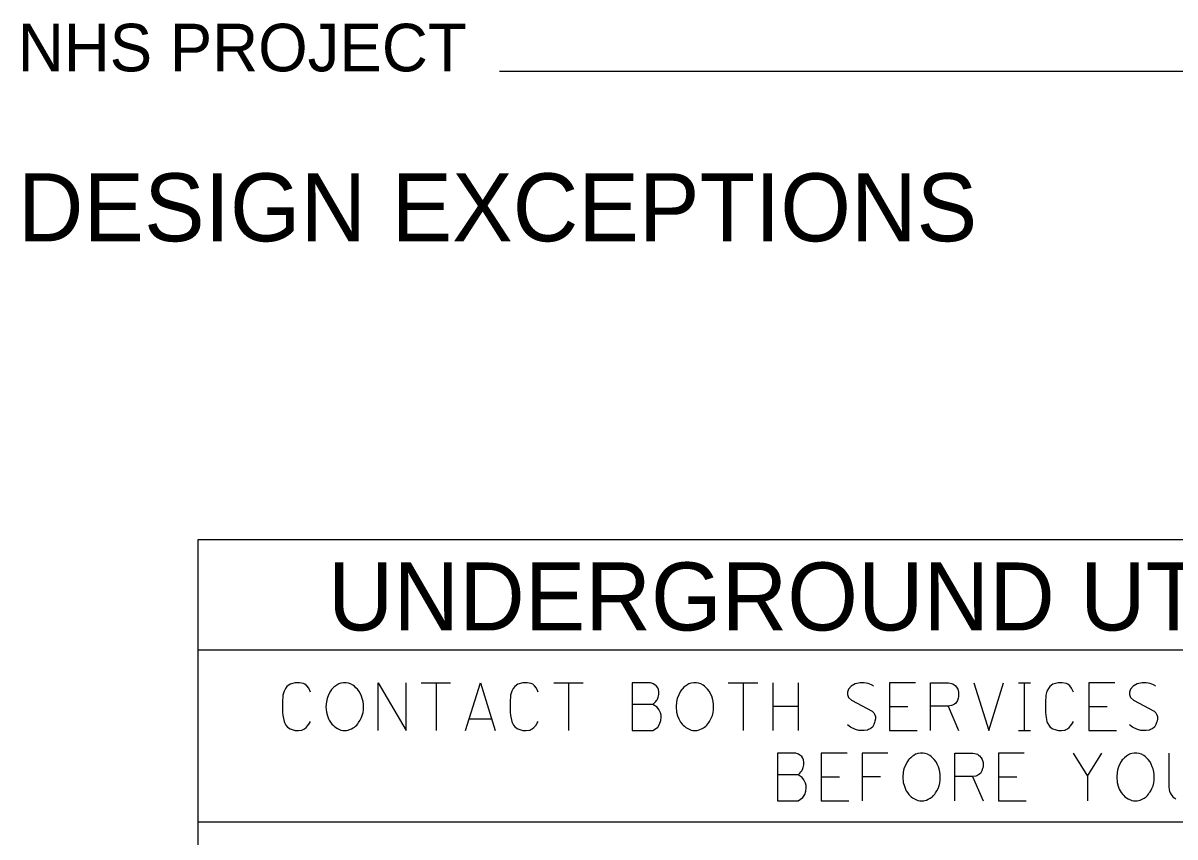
# Model space of a CAD drawing. Extents: x -97 to 34, y -21 to 22.
# Drawn here: x -97.447 to -94.056, y -17.539 to -15.144 of the extents above; entities that cross this region are included whole.
import ezdxf

# ---------------------------------------------------------------- set-up
doc = ezdxf.new("R2010")
doc.units = 0
doc.layers.add('SH_Data', color=7, linetype='Continuous')

msp = doc.modelspace()

# ---------------------------------------------------------------- linework, layer by layer
at = {"layer": 'SH_Data'}
for p, q in [((-91.8195, -15.2865), (-96.0447, -15.2865)), ((-96.9313, -16.9884), (-91.7313, -16.9884)), ((-96.275, -17.0854), (-96.188, -17.0854)), ((-96.2309, -17.0854), (-96.2309, -17.2254)), ((-95.8848, -17.0854), (-95.7978, -17.0854)), ((-95.8407, -17.0854), (-95.8407, -17.2254)), ((-95.3712, -17.0854), (-95.2841, -17.0854)), ((-95.3271, -17.0854), (-95.3271, -17.2254)), ((-95.24, -17.0854), (-95.24, -17.2254)), ((-95.164, -17.2254), (-95.164, -17.0854)), ((-94.5169, -17.0854), (-94.4817, -17.0854)), ((-94.4993, -17.2254), (-94.4993, -17.0854)), ((-95.164, -17.1549), (-95.24, -17.1549)), ((-94.8961, -17.1549), (-94.8421, -17.1549)), ((-94.7242, -17.1538), (-94.6933, -17.2254)), ((-94.3097, -17.1549), (-94.2557, -17.1549)), ((-96.0678, -17.1923), (-96.1328, -17.1923)), ((-94.5169, -17.2254), (-94.4817, -17.2254)), ((-95.0974, -17.3619), (-95.0434, -17.3619)), ((-94.9773, -17.3608), (-94.9233, -17.3608)), ((-94.6521, -17.3608), (-94.6212, -17.4325)), ((-94.576, -17.3619), (-94.522, -17.3619)), ((-94.3137, -17.3597), (-94.3137, -17.4325)), ((-96.9313, -17.4942), (-91.7313, -17.4942))]:
    msp.add_line(p, q, dxfattribs=at)
msp.add_lwpolyline([(-96.9313, -16.6633), (-91.7313, -16.6633), (-91.7313, -19.7633), (-96.9313, -19.7633)], close=True, dxfattribs=at)
msp.add_lwpolyline([(-96.9313, -16.6633), (-91.7313, -16.6633), (-91.7313, -19.7633), (-96.9313, -19.7633)], close=True, dxfattribs=at)
for points in [[(-96.6002, -17.113), (-96.6057, -17.1008), (-96.6112, -17.0942), (-96.6167, -17.0898), (-96.6212, -17.0876), (-96.6333, -17.0854), (-96.6454, -17.0854), (-96.6608, -17.0898), (-96.6697, -17.0964), (-96.6741, -17.1019), (-96.6785, -17.1097), (-96.6818, -17.1218), (-96.6829, -17.1438), (-96.6829, -17.1604), (-96.6829, -17.1714), (-96.6818, -17.1813), (-96.6785, -17.1989), (-96.6774, -17.2023), (-96.673, -17.21), (-96.6686, -17.2155), (-96.6608, -17.221), (-96.6542, -17.2232), (-96.6454, -17.2254), (-96.6355, -17.2254), (-96.6256, -17.2243), (-96.6223, -17.2232), (-96.6179, -17.221), (-96.6134, -17.2166), (-96.6079, -17.2111), (-96.6035, -17.2045), (-96.6002, -17.1989)], [(-96.5109, -17.0865), (-96.5142, -17.0876), (-96.5175, -17.0887), (-96.5231, -17.092), (-96.5264, -17.0942), (-96.5319, -17.0986), (-96.5363, -17.1031), (-96.5385, -17.1053), (-96.5418, -17.1097), (-96.5473, -17.1207), (-96.5517, -17.1317), (-96.5539, -17.1416), (-96.555, -17.156), (-96.5539, -17.1714), (-96.5506, -17.1824), (-96.5473, -17.1912), (-96.5451, -17.1956), (-96.5418, -17.2011), (-96.5374, -17.2067), (-96.5341, -17.21), (-96.5308, -17.2133), (-96.5264, -17.2166), (-96.5209, -17.2199), (-96.5109, -17.2243), (-96.5054, -17.2254), (-96.4944, -17.2254), (-96.49, -17.2243), (-96.4856, -17.2232), (-96.4801, -17.221), (-96.4746, -17.2177), (-96.4712, -17.2155), (-96.4679, -17.2133), (-96.4646, -17.21), (-96.4613, -17.2056), (-96.4591, -17.2023), (-96.4569, -17.1989), (-96.4547, -17.1956), (-96.4514, -17.189), (-96.4481, -17.1813), (-96.4459, -17.1725), (-96.4448, -17.1648), (-96.4448, -17.1637), (-96.4448, -17.156), (-96.4448, -17.1494), (-96.4459, -17.1405), (-96.4481, -17.1317), (-96.4503, -17.1251), (-96.4536, -17.1174), (-96.4569, -17.1108), (-96.4624, -17.1041), (-96.4668, -17.0997), (-96.4712, -17.0953), (-96.4756, -17.092), (-96.4823, -17.0887), (-96.4889, -17.0865), (-96.4955, -17.0854), (-96.5032, -17.0854), (-96.5109, -17.0865)], [(-96.4018, -17.2254), (-96.4018, -17.0854), (-96.3191, -17.2254), (-96.3191, -17.0854)], [(-96.1439, -17.2254), (-96.0998, -17.0854), (-96.0568, -17.2254)], [(-95.93, -17.113), (-95.9355, -17.1008), (-95.9411, -17.0942), (-95.9466, -17.0898), (-95.951, -17.0876), (-95.9631, -17.0854), (-95.9752, -17.0854), (-95.9907, -17.0898), (-95.9995, -17.0964), (-96.0039, -17.1019), (-96.0083, -17.1097), (-96.0116, -17.1218), (-96.0127, -17.1438), (-96.0127, -17.1604), (-96.0127, -17.1714), (-96.0116, -17.1813), (-96.0083, -17.1989), (-96.0072, -17.2023), (-96.0028, -17.21), (-95.9984, -17.2155), (-95.9907, -17.221), (-95.984, -17.2232), (-95.9752, -17.2254), (-95.9653, -17.2254), (-95.9554, -17.2243), (-95.9521, -17.2232), (-95.9477, -17.221), (-95.9433, -17.2166), (-95.9377, -17.2111), (-95.9333, -17.2045), (-95.93, -17.1989)], [(-95.5928, -17.1494), (-95.5872, -17.1438), (-95.5839, -17.1405), (-95.5817, -17.1372), (-95.5806, -17.135), (-95.5784, -17.1306), (-95.5773, -17.1273), (-95.5751, -17.1196), (-95.5751, -17.1163), (-95.5751, -17.1119), (-95.5762, -17.1053), (-95.5784, -17.0997), (-95.5817, -17.0953), (-95.5872, -17.0909), (-95.5916, -17.0887), (-95.5938, -17.0876), (-95.5994, -17.0854), (-95.6534, -17.0854), (-95.6534, -17.2254), (-95.5928, -17.2254), (-95.585, -17.221), (-95.5784, -17.2155), (-95.5729, -17.2067), (-95.5696, -17.1967), (-95.5685, -17.1868), (-95.5685, -17.1802), (-95.5707, -17.1736), (-95.5751, -17.1637), (-95.5806, -17.1571), (-95.5928, -17.1494), (-95.6534, -17.1494)], [(-95.4803, -17.0865), (-95.4836, -17.0876), (-95.4869, -17.0887), (-95.4925, -17.092), (-95.4957, -17.0942), (-95.5013, -17.0986), (-95.5057, -17.1031), (-95.5079, -17.1053), (-95.5112, -17.1097), (-95.5167, -17.1207), (-95.5211, -17.1317), (-95.5233, -17.1416), (-95.5244, -17.156), (-95.5233, -17.1714), (-95.52, -17.1824), (-95.5167, -17.1912), (-95.5145, -17.1956), (-95.5112, -17.2011), (-95.5068, -17.2067), (-95.5035, -17.21), (-95.5002, -17.2133), (-95.4957, -17.2166), (-95.4902, -17.2199), (-95.4803, -17.2243), (-95.4748, -17.2254), (-95.4638, -17.2254), (-95.4594, -17.2243), (-95.455, -17.2232), (-95.4495, -17.221), (-95.444, -17.2177), (-95.4406, -17.2155), (-95.4373, -17.2133), (-95.434, -17.21), (-95.4307, -17.2056), (-95.4285, -17.2023), (-95.4263, -17.1989), (-95.4241, -17.1956), (-95.4208, -17.189), (-95.4175, -17.1813), (-95.4153, -17.1725), (-95.4142, -17.1648), (-95.4142, -17.1637), (-95.4142, -17.156), (-95.4142, -17.1494), (-95.4153, -17.1405), (-95.4175, -17.1317), (-95.4197, -17.1251), (-95.423, -17.1174), (-95.4263, -17.1108), (-95.4318, -17.1041), (-95.4362, -17.0997), (-95.4406, -17.0953), (-95.445, -17.092), (-95.4517, -17.0887), (-95.4583, -17.0865), (-95.4649, -17.0854), (-95.4726, -17.0854), (-95.4803, -17.0865)], [(-94.9435, -17.0953), (-94.9457, -17.0931), (-94.949, -17.0909), (-94.959, -17.0876), (-94.9711, -17.0854), (-94.9799, -17.0854), (-94.9832, -17.0854), (-94.9975, -17.0887), (-95.0097, -17.0953), (-95.0174, -17.1041), (-95.0196, -17.113), (-95.0196, -17.1196), (-95.0174, -17.1284), (-95.0086, -17.1361), (-94.9479, -17.1692), (-94.9424, -17.1736), (-94.9402, -17.178), (-94.938, -17.1846), (-94.938, -17.1912), (-94.9391, -17.1979), (-94.9402, -17.2023), (-94.9424, -17.2078), (-94.9446, -17.2122), (-94.9468, -17.2155), (-94.9501, -17.2188), (-94.9534, -17.221), (-94.9578, -17.2232), (-94.9612, -17.2243), (-94.9711, -17.2254), (-94.9865, -17.2254), (-94.9964, -17.2232), (-95.0108, -17.2155), (-95.0196, -17.2089)], [(-94.8201, -17.0854), (-94.8961, -17.0854), (-94.8961, -17.2254), (-94.8145, -17.2254)], [(-94.776, -17.2254), (-94.776, -17.0854), (-94.7231, -17.0854), (-94.7176, -17.0865), (-94.7098, -17.0887), (-94.7065, -17.0909), (-94.7032, -17.0931), (-94.6988, -17.0986), (-94.6955, -17.1041), (-94.6933, -17.113), (-94.6933, -17.1262), (-94.6944, -17.1306), (-94.6966, -17.1372), (-94.701, -17.1449), (-94.7054, -17.1482), (-94.7087, -17.1504), (-94.711, -17.1516), (-94.7142, -17.1526), (-94.7242, -17.1538), (-94.776, -17.1538)], [(-94.6481, -17.0854), (-94.604, -17.2254), (-94.561, -17.0854)], [(-94.3549, -17.113), (-94.3604, -17.1008), (-94.3659, -17.0942), (-94.3714, -17.0898), (-94.3759, -17.0876), (-94.388, -17.0854), (-94.4001, -17.0854), (-94.4155, -17.0898), (-94.4244, -17.0964), (-94.4288, -17.1019), (-94.4332, -17.1097), (-94.4365, -17.1218), (-94.4376, -17.1438), (-94.4376, -17.1604), (-94.4376, -17.1714), (-94.4365, -17.1813), (-94.4332, -17.1989), (-94.4321, -17.2023), (-94.4277, -17.21), (-94.4233, -17.2155), (-94.4155, -17.221), (-94.4089, -17.2232), (-94.4001, -17.2254), (-94.3902, -17.2254), (-94.3803, -17.2243), (-94.377, -17.2232), (-94.3726, -17.221), (-94.3681, -17.2166), (-94.3626, -17.2111), (-94.3582, -17.2045), (-94.3549, -17.1989)], [(-94.2337, -17.0854), (-94.3097, -17.0854), (-94.3097, -17.2254), (-94.2281, -17.2254)], [(-94.1135, -17.0953), (-94.1157, -17.0931), (-94.119, -17.0909), (-94.129, -17.0876), (-94.1411, -17.0854), (-94.1499, -17.0854), (-94.1532, -17.0854), (-94.1675, -17.0887), (-94.1797, -17.0953), (-94.1874, -17.1041), (-94.1896, -17.113), (-94.1896, -17.1196), (-94.1874, -17.1284), (-94.1786, -17.1361), (-94.1179, -17.1692), (-94.1124, -17.1736), (-94.1102, -17.178), (-94.108, -17.1846), (-94.108, -17.1912), (-94.1091, -17.1979), (-94.1102, -17.2023), (-94.1124, -17.2078), (-94.1146, -17.2122), (-94.1168, -17.2155), (-94.1201, -17.2188), (-94.1234, -17.221), (-94.1278, -17.2232), (-94.1312, -17.2243), (-94.1411, -17.2254), (-94.1565, -17.2254), (-94.1664, -17.2232), (-94.1808, -17.2155), (-94.1896, -17.2089)], [(-95.1657, -17.3564), (-95.1602, -17.3509), (-95.1569, -17.3476), (-95.1547, -17.3443), (-95.1536, -17.3421), (-95.1514, -17.3377), (-95.1503, -17.3344), (-95.1481, -17.3266), (-95.1481, -17.3233), (-95.1481, -17.3189), (-95.1492, -17.3123), (-95.1514, -17.3068), (-95.1547, -17.3024), (-95.1602, -17.298), (-95.1646, -17.2958), (-95.1668, -17.2947), (-95.1724, -17.2925), (-95.2264, -17.2925), (-95.2264, -17.4325), (-95.1657, -17.4325), (-95.158, -17.4281), (-95.1514, -17.4226), (-95.1459, -17.4137), (-95.1426, -17.4038), (-95.1415, -17.3939), (-95.1415, -17.3873), (-95.1437, -17.3807), (-95.1481, -17.3707), (-95.1536, -17.3641), (-95.1657, -17.3564), (-95.2264, -17.3564)], [(-95.0213, -17.2925), (-95.0974, -17.2925), (-95.0974, -17.4325), (-95.0158, -17.4325)], [(-94.9012, -17.2925), (-94.9773, -17.2925), (-94.9773, -17.4325)], [(-94.813, -17.2936), (-94.8163, -17.2947), (-94.8196, -17.2958), (-94.8252, -17.2991), (-94.8285, -17.3013), (-94.834, -17.3057), (-94.8384, -17.3101), (-94.8406, -17.3123), (-94.8439, -17.3167), (-94.8494, -17.3278), (-94.8538, -17.3388), (-94.856, -17.3487), (-94.8571, -17.363), (-94.856, -17.3785), (-94.8527, -17.3895), (-94.8494, -17.3983), (-94.8472, -17.4027), (-94.8439, -17.4082), (-94.8395, -17.4137), (-94.8362, -17.417), (-94.8329, -17.4204), (-94.8285, -17.4236), (-94.823, -17.427), (-94.813, -17.4314), (-94.8075, -17.4325), (-94.7965, -17.4325), (-94.7921, -17.4314), (-94.7877, -17.4303), (-94.7822, -17.4281), (-94.7767, -17.4248), (-94.7733, -17.4226), (-94.77, -17.4204), (-94.7667, -17.417), (-94.7634, -17.4126), (-94.7612, -17.4093), (-94.759, -17.406), (-94.7568, -17.4027), (-94.7535, -17.3961), (-94.7502, -17.3884), (-94.748, -17.3796), (-94.7469, -17.3718), (-94.7469, -17.3707), (-94.7469, -17.363), (-94.7469, -17.3564), (-94.748, -17.3476), (-94.7502, -17.3388), (-94.7524, -17.3322), (-94.7557, -17.3244), (-94.759, -17.3178), (-94.7645, -17.3112), (-94.7689, -17.3068), (-94.7733, -17.3024), (-94.7777, -17.2991), (-94.7844, -17.2958), (-94.791, -17.2936), (-94.7976, -17.2925), (-94.8053, -17.2925), (-94.813, -17.2936)], [(-94.7039, -17.4325), (-94.7039, -17.2925), (-94.651, -17.2925), (-94.6455, -17.2936), (-94.6377, -17.2958), (-94.6345, -17.298), (-94.6311, -17.3002), (-94.6267, -17.3057), (-94.6234, -17.3112), (-94.6212, -17.32), (-94.6212, -17.3333), (-94.6223, -17.3377), (-94.6245, -17.3443), (-94.6289, -17.352), (-94.6333, -17.3553), (-94.6367, -17.3575), (-94.6389, -17.3586), (-94.6422, -17.3597), (-94.6521, -17.3608), (-94.7039, -17.3608)], [(-94.5, -17.2925), (-94.576, -17.2925), (-94.576, -17.4325), (-94.4945, -17.4325)], [(-94.3556, -17.2925), (-94.3137, -17.3597), (-94.2718, -17.2925)], [(-94.1836, -17.2936), (-94.1869, -17.2947), (-94.1902, -17.2958), (-94.1958, -17.2991), (-94.1991, -17.3013), (-94.2046, -17.3057), (-94.209, -17.3101), (-94.2112, -17.3123), (-94.2145, -17.3167), (-94.22, -17.3278), (-94.2244, -17.3388), (-94.2266, -17.3487), (-94.2277, -17.363), (-94.2266, -17.3785), (-94.2233, -17.3895), (-94.22, -17.3983), (-94.2178, -17.4027), (-94.2145, -17.4082), (-94.2101, -17.4137), (-94.2068, -17.417), (-94.2035, -17.4204), (-94.1991, -17.4236), (-94.1936, -17.427), (-94.1836, -17.4314), (-94.1781, -17.4325), (-94.1671, -17.4325), (-94.1627, -17.4314), (-94.1583, -17.4303), (-94.1528, -17.4281), (-94.1473, -17.4248), (-94.1439, -17.4226), (-94.1406, -17.4204), (-94.1373, -17.417), (-94.134, -17.4126), (-94.1318, -17.4093), (-94.1296, -17.406), (-94.1274, -17.4027), (-94.1241, -17.3961), (-94.1208, -17.3884), (-94.1186, -17.3796), (-94.1175, -17.3718), (-94.1175, -17.3707), (-94.1175, -17.363), (-94.1175, -17.3564), (-94.1186, -17.3476), (-94.1208, -17.3388), (-94.123, -17.3322), (-94.1263, -17.3244), (-94.1296, -17.3178), (-94.1351, -17.3112), (-94.1395, -17.3068), (-94.1439, -17.3024), (-94.1483, -17.2991), (-94.155, -17.2958), (-94.1616, -17.2936), (-94.1682, -17.2925), (-94.1759, -17.2925), (-94.1836, -17.2936)], [(-94.0745, -17.2925), (-94.0745, -17.3906), (-94.0734, -17.4005), (-94.0723, -17.4038), (-94.0701, -17.4093), (-94.0679, -17.4137), (-94.0646, -17.4181), (-94.0624, -17.4204), (-94.0613, -17.4214), (-94.0568, -17.4248), (-94.0536, -17.427)]]:
    msp.add_lwpolyline(points, dxfattribs=at)

# ---------------------------------------------------------------- texts
for s, height, p in [('NHS PROJECT', 0.14, (-97.4619, -15.2865)), ('DESIGN EXCEPTIONS', 0.2, (-97.4619, -15.7865)), ('UNDERGROUND UTILITIES', 0.2, (-96.5494, -16.9313))]:
    msp.add_text(s, height=height, dxfattribs=at).set_placement(p)

doc.saveas('drawing.dxf')
